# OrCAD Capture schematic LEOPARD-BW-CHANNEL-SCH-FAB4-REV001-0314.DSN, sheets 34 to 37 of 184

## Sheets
34 145_PVCCIN_CPU1_MOSFET_1: size C; title: PVCCIN_CPU1_MOSFET_1
35 144_PVCCIN_CPU1_Controller: size A3; title: PVCCIN_CPU1_CONTROLLER
36 143_PVCCIN_CPU0_Decoupling: size A3; title: PVCCIN_CPU0_DECOUPLING
37 142_PVCCIN_CPU0_MOSFET_2: size C; title: PVCCIN_CPU0_MOSFET_2

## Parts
sheet 142_PVCCIN_CPU0_MOSFET_2
PC1376  SCD47U25V3KX-3-GP  [C603H36]
PC1377  SC10U16V5KX-1-GP  [C805H54]
PC1378  SC10U16V5KX-1-GP  [C805H54]
PC1379  SC10U16V5KX-1-GP  [C805H54]
PC1380  SC1U10V2KX-4-GP  [C402H22]
PC1381  SCD22U16V2KX-GP  [C402H22]
PC1382  SC1U10V2KX-4-GP  [C402H22]
PC1383  SCD47U25V3KX-3-GP  [C603H36]
PC1384  SC10U16V5KX-1-GP  [C805H54]
PC1385  SC10U16V5KX-1-GP  [C805H54]
PC1386  SC10U16V5KX-1-GP  [C805H54]
PC1387  SCD22U16V2KX-GP  [C402H22]
PC1388  SC1U10V2KX-4-GP  [C402H22]
PC1406  SCD1U16V2KX-3GP  [C402H22]
PC1407  SC1U25V3KX-GP  [C603H36]
PC1408  SC1U25V3KX-GP  [C603H36]
PC1409  SCD1U16V2KX-3GP  [C402H22]
PC1410  SC1U10V2KX-4-GP  [C402H22]
PC1436  SCD1U16V2KX-3GP  [C402H22]
PC1437  SCD1U16V2KX-3GP  [C402H22]
PG35  COPPER-CLOSE-GP-U  [CON2C-U]
PG36  COPPER-CLOSE-GP-U  [CON2C-U]
PG39  COPPER-CLOSE-GP-U  [CON2C-U]
PG40  COPPER-CLOSE-GP-U  [CON2C-U]
PL78  IND-150NH-15-GP  [L102078-254224H296]
PL79  IND-150NH-15-GP  [L102078-254224H296]
PR27  0R2J-2-GP  [R402H16]
PR28  0R2J-2-GP  [R402H16]
PR45  0R2J-2-GP  [R402H16]
PR46  0R2J-2-GP  [R402H16]
PR2183  1R2F-GP  [R402H16]
PR2187  1R2F-GP  [R402H16]
PR2219  0R3J-6-GP  [R603H22]
PR2221  0R3J-6-GP  [R603H22]
PR2230  10KR2F-2-GP  [R402H16]
PR2231  10KR2F-2-GP  [R402H16]
PR6633  562R2F-GP  [R402H16]
PR6634  562R2F-GP  [R402H16]
PR6635  562R2F-GP  [R402H16]
PR6636  562R2F-GP  [R402H16]
PTP13  TPAD24  [TPAD24]
PTP14  TPAD24  [TPAD24]
PTP15  TPAD24  [TPAD24]
PTP16  TPAD24  [TPAD24]
PU181  TDA21232-GP  [QFN31G5-G4P-7H38]
PU182  TDA21232-GP  [QFN31G5-G4P-7H38]
sheet 143_PVCCIN_CPU0_Decoupling
PC38  SC1U10V2KX-4-GP  [C402H22]
PC39  SC1U10V2KX-4-GP  [C402H22]
PC1149  SC22U6D3V5MX-5-GP  [C805H56]
PC1150  SC22U6D3V5MX-5-GP  [C805H56]
PC1151  SC22U6D3V5MX-5-GP  [C805H56]
PC1152  SC22U6D3V5MX-5-GP  [C805H56]
PC1153  SC22U6D3V5MX-5-GP  [C805H56]
PC1154  SC22U6D3V5MX-5-GP  [C805H56]
PC1155  SC22U6D3V5MX-5-GP  [C805H56]
PC1156  SC22U6D3V5MX-5-GP  [C805H56]
PC1157  SC22U6D3V5MX-5-GP  [C805H56]
PC1158  SC22U6D3V5MX-5-GP  [C805H56]
PC1159  SC22U6D3V5MX-5-GP  [C805H56]
PC1160  SC22U6D3V5MX-5-GP  [C805H56]
PC1161  ST470U2D5VDM-13-GP  [CT7343H83]
PC1162  ST470U2D5VDM-13-GP  [CT7343H83]
PC1163  ST470U2D5VDM-13-GP  [CT7343H83]
PC1164  ST470U2D5VDM-13-GP  [CT7343H83]
PC1165  ST470U2D5VDM-13-GP  [CT7343H83]
PC1166  ST470U2D5VDM-13-GP  [CT7343H83]
PC1167  SC22U6D3V5MX-5-GP  [C805H56]
PC1168  SC22U6D3V5MX-5-GP  [C805H56]
PC1169  SC22U6D3V5MX-5-GP  [C805H56]
PC1170  SC22U6D3V5MX-5-GP  [C805H56]
PC1171  SC22U6D3V5MX-5-GP  [C805H56]
PC1172  SC22U6D3V5MX-5-GP  [C805H56]
PC1173  SC22U6D3V5MX-5-GP  [C805H56]
PC1174  SC22U6D3V5MX-5-GP  [C805H56]
PC1175  SC22U6D3V5MX-5-GP  [C805H56]
PC1176  SC22U6D3V5MX-5-GP  [C805H56]
PC1177  SC22U6D3V5MX-5-GP  [C805H56]
PC1178  SC22U6D3V5MX-5-GP  [C805H56]
PC1179  SC22U6D3V5MX-5-GP  [C805H56]
PC1180  SC22U6D3V5MX-5-GP  [C805H56]
PC1181  SC22U6D3V5MX-5-GP  [C805H56]
PC1182  SC22U6D3V5MX-5-GP  [C805H56]
PC1183  SC22U6D3V5MX-5-GP  [C805H56]
PC1184  SC47U4V5MX-2-GP  [C805H58]
PC1185  SC47U4V5MX-2-GP  [C805H58]
PC1186  SC47U4V5MX-2-GP  [C805H58]
PC1187  SC47U4V5MX-2-GP  [C805H58]
PC1188  SC47U4V5MX-2-GP  [C805H58]
PC1189  SC22U6D3V5MX-5-GP  [C805H56]
PC1190  SC22U6D3V5MX-5-GP  [C805H56]
PC1191  SC22U6D3V5MX-5-GP  [C805H56]
PC1192  SC22U6D3V5MX-5-GP  [C805H56]
PC1193  SC22U6D3V5MX-5-GP  [C805H56]
PC1194  SC22U6D3V5MX-5-GP  [C805H56]
PC1195  SC22U6D3V5MX-5-GP  [C805H56]
PC1196  SC22U6D3V5MX-5-GP  [C805H56]
PC1197  SC22U6D3V5MX-5-GP  [C805H56]
PC1198  SC22U6D3V5MX-5-GP  [C805H56]
PC1199  SC22U6D3V5MX-5-GP  [C805H56]
PC1200  SC22U6D3V5MX-5-GP  [C805H56]
PC1201  SC47U4V5MX-2-GP  [C805H58]
PC1202  SC47U4V5MX-2-GP  [C805H58]
PC1203  SC47U4V5MX-2-GP  [C805H58]
PC1204  SC47U4V5MX-2-GP  [C805H58]
PC1205  SC47U4V5MX-2-GP  [C805H58]
PC1206  SC47U4V5MX-2-GP  [C805H58]
PC1207  SC47U4V5MX-2-GP  [C805H58]
PC1208  SC47U4V5MX-2-GP  [C805H58]
PC1209  SC47U4V5MX-2-GP  [C805H58]
PC1210  SC47U4V5MX-2-GP  [C805H58]
PC1211  SC47U4V5MX-2-GP  [C805H58]
PC1212  SC47U4V5MX-2-GP  [C805H58]
PC1213  SC47U4V5MX-2-GP  [C805H58]
PC1214  SC47U4V5MX-2-GP  [C805H58]
PC1215  SC47U4V5MX-2-GP  [C805H58]
PC1216  SC47U4V5MX-2-GP  [C805H58]
PC1217  SC47U4V5MX-2-GP  [C805H58]
PC1218  SCD1U25V5KX-1GP  [C805H54]
PC1219  SC1U25V6KX-2GP  [C1206H45]
PC1220  SCD1U25V5KX-1GP  [C805H54]
PL60  IND-105NH-GP  [L7065-245152H195]
PR1949  100R2F-L1-GP-U  [R402H14]
PR1950  100R2F-L1-GP-U  [R402H14]
PTC15  E270U16VM-28-GP  [ECAP-100D6D3H363]
PTC16  E270U16VM-28-GP  [ECAP-100D6D3H363]
R6618  100R3F-1-GP  [R603H22]
sheet 144_PVCCIN_CPU1_Controller
PC1223  SC1U10V2KX-4-GP  [C402H22]
PC1224  SCD1U16V2KX-3GP  [C402H22]
PC1225  SC1U10V2KX-4-GP  [C402H22]
PC1226  SCD1U16V2KX-3GP  [C402H22]
PC1230  SC1KP50V2KX-1GP  [C402H22]
PC1231  SC10U4V3MX-3-GP  [C603H40]
PC1232  SC220P50V2KX-3GP  [C402H22]
PC1233  SCD1U16V2KX-3GP  [C402H22]
PC1460  SC220P50V2JN-3GP  [C402H22]
PC1586  SC220P50V2JN-3GP  [C402H22]
PC7326  SCD47U6D3V2KX-1-GP  [C402H22]
PC7327  SCD47U6D3V2KX-1-GP  [C402H22]
PC7328  SCD47U6D3V2KX-1-GP  [C402H22]
PC7329  SCD47U6D3V2KX-1-GP  [C402H22]
PC7330  SCD47U6D3V2KX-1-GP  [C402H22]
PQ7  NST3906F3T5G-GP-U  [SOT-1123CBE1006-1H16]
PR1937  0R2J-2-GP  [R402H16]
PR1951  0R2J-2-GP  [R402H16]
PR1952  10KR2F-2-GP  [R402H16]
PR1954  1KR2F-3-GP  [R402H16]
PR1955  1KR2F-3-GP  [R402H16]
PR1956  0R2J-2-GP  [R402H16]
PR1957  0R2J-2-GP  [R402H16]
PR1958  0R2J-2-GP  [R402H16]
PR1962  16KR2F-GP  [R402H16]
PR1963  16KR2F-GP  [R402H16]
PR1964  16KR2F-GP  [R402H16]
PR1965  19K1R2F-GP  [R402H16]
PR1966  1KR2F-3-GP  [R402H16]
PR1967  10R3F-GP  [R603H22]
PR1969  0R0402-PAD-1-GP  [0R0402-PAD]
PR1971  49D9R2F-GP  [R402H16]
PR1972  100R2F-L1-GP-U  [R402H14]
PR1973  82R2J-1-GP  [R402H16]
PR1974  0R2J-2-GP  [R402H16]
PR1975  0R2J-2-GP  [R402H16]
PR1976  150R2F-1-GP  [R402H16]
PTP2  TPAD24  [TPAD24]
PU7  PX3746HDN-GP  [QFN48J6-G3437H36]
sheet 145_PVCCIN_CPU1_MOSFET_1
PC1411  SCD47U25V3KX-3-GP  [C603H36]
PC1412  SC10U16V5KX-1-GP  [C805H54]
PC1413  SC10U16V5KX-1-GP  [C805H54]
PC1414  SC10U16V5KX-1-GP  [C805H54]
PC1415  SCD1U16V2KX-3GP  [C402H22]
PC1416  SC1U25V3KX-GP  [C603H36]
PC1417  SCD22U16V2KX-GP  [C402H22]
PC1418  SC1U10V2KX-4-GP  [C402H22]
PC1419  SC1U10V2KX-4-GP  [C402H22]
PC1420  SCD47U25V3KX-3-GP  [C603H36]
PC1421  SC10U16V5KX-1-GP  [C805H54]
PC1422  SC10U16V5KX-1-GP  [C805H54]
PC1438  SCD1U16V2KX-3GP  [C402H22]
PC1439  SC10U16V5KX-1-GP  [C805H54]
PC1440  SCD1U16V2KX-3GP  [C402H22]
PC1441  SC1U25V3KX-GP  [C603H36]
PC1442  SCD1U16V2KX-3GP  [C402H22]
PC1443  SC1U10V2KX-4-GP  [C402H22]
PC1444  SCD22U16V2KX-GP  [C402H22]
PC1445  SC1U10V2KX-4-GP  [C402H22]
PC1446  SCD47U25V3KX-3-GP  [C603H36]
PC1447  SC10U16V5KX-1-GP  [C805H54]
PC1448  SC10U16V5KX-1-GP  [C805H54]
PC1449  SC10U16V5KX-1-GP  [C805H54]
PC1450  SCD1U16V2KX-3GP  [C402H22]
PC1451  SC1U25V3KX-GP  [C603H36]
PC1452  SCD1U16V2KX-3GP  [C402H22]
PC1453  SCD22U16V2KX-GP  [C402H22]
PC1454  SC1U10V2KX-4-GP  [C402H22]
PC1455  SC1U10V2KX-4-GP  [C402H22]
PG41  COPPER-CLOSE-GP-U  [CON2C-U]
PG42  COPPER-CLOSE-GP-U  [CON2C-U]
PG47  COPPER-CLOSE-GP-U  [CON2C-U]
PG48  COPPER-CLOSE-GP-U  [CON2C-U]
PG55  COPPER-CLOSE-GP-U  [CON2C-U]
PG56  COPPER-CLOSE-GP-U  [CON2C-U]
PL80  IND-150NH-15-GP  [L102078-254224H296]
PL81  IND-150NH-15-GP  [L102078-254224H296]
PL82  IND-150NH-15-GP  [L102078-254224H296]
PR29  0R2J-2-GP  [R402H16]
PR30  0R2J-2-GP  [R402H16]
PR31  0R2J-2-GP  [R402H16]
PR47  0R2J-2-GP  [R402H16]
PR48  0R2J-2-GP  [R402H16]
PR49  0R2J-2-GP  [R402H16]
PR2190  1R2F-GP  [R402H16]
PR2193  1R2F-GP  [R402H16]
PR2196  1R2F-GP  [R402H16]
PR2223  0R3J-6-GP  [R603H22]
PR2225  0R3J-6-GP  [R603H22]
PR2232  10KR2F-2-GP  [R402H16]
PR2233  10KR2F-2-GP  [R402H16]
PR2234  10KR2F-2-GP  [R402H16]
PR2237  0R3J-6-GP  [R603H22]
PR6637  562R2F-GP  [R402H16]
PR6638  562R2F-GP  [R402H16]
PR6639  562R2F-GP  [R402H16]
PR6640  562R2F-GP  [R402H16]
PR6641  562R2F-GP  [R402H16]
PR6642  562R2F-GP  [R402H16]
PTP17  TPAD24  [TPAD24]
PTP18  TPAD24  [TPAD24]
PTP19  TPAD24  [TPAD24]
PTP20  TPAD24  [TPAD24]
PTP21  TPAD24  [TPAD24]
PTP22  TPAD24  [TPAD24]
PU183  TDA21232-GP  [QFN31G5-G4P-7H38]
PU184  TDA21232-GP  [QFN31G5-G4P-7H38]
PU185  TDA21232-GP  [QFN31G5-G4P-7H38]

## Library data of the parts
PC1376 PC1383 PC1411 PC1420 PC1446 = SCD47U25V3KX-3-GP: CHIP CAP C 0.47U 25V K0603 X7R; GREENDFACTOR: R2_SA;HF_SA;G_SA;; Part Number: 78.47422.2BL; Part Type: SMD-BCG5; SPEC: http://wpqssvr.wistron.com.tw:7001/wpqs/servlet/COM.qpart.Attachment?PartNumber=78.47422.2BL
PC1377-PC1379 PC1384-PC1386 PC1412-PC1414 PC1421 PC1422 PC1439 PC1447-PC1449 = SC10U16V5KX-1-GP: CHIP CAP C 10U 16V K0805 X6S; GREENDFACTOR: R2_SA;; Package Type: SMD-BCG5; Part Number: 78.10621.81L; SPEC: http://wpqssvr.wistron.com.tw:7001/wpqs/servlet/COM.qpart.Attachment?PartNumber=78.10621.81L
PC1223 PC1225 PC1380 PC1382 PC1388 PC1410 PC1418 PC1419 PC1443 PC1445 PC1454 PC1455 = SC1U10V2KX-4-GP: CHIP CAP C 1U 10V K 0402 X6S; GREENDFACTOR: R2_SA;HF_SA;; Package Type: SMD-BCG6; Part Number: 78.10523.8FL; SPEC: http://wpqssvr.wistron.com.tw:7001/wpqs/servlet/COM.qpart.Attachment?PartNumber=78.10523.8FL
PC1381 PC1387 PC1417 PC1444 PC1453 = SCD22U16V2KX-GP: CHIP CAP C 0.22U 16V K0402 X7R; GREENDFACTOR: R2_SA;HF_SA;G_SA;; Package Type: SMD-BCG4; Part Number: 78.22421.2FL; SPEC: http://wpqssvr.wistron.com.tw:7001/wpqs/servlet/COM.qpart.Attachment?PartNumber=78.22421.2FL; Size: 0402; Type: X7R
PC1406 PC1409 PC1415 PC1436-PC1438 PC1440 PC1442 PC1450 PC1452 = SCD1U16V2KX-3GP: CHIP CAP C 0.1U 16V K0402 X7R; GREENDFACTOR: R2_SA;HF_SA;G_SA;; MAIN_SOURCE: M; Package Type: SMD-BCG; Part Number: 78.10421.2FL; SPEC: http://wpqssvr.wistron.com.tw:7001/wpqs/servlet/COM.qpart.Attachment?PartNumber=78.10421.2FL; Size: 0402; Type: X7R
PC1407 PC1408 PC1416 PC1441 PC1451 = SC1U25V3KX-GP: CHIP CAP C 1U 25V K0603 X7R; GREENDFACTOR: R2_SA;HF_SA;G_SA;; Package Type: SMD-BCG; Part Number: 78.10522.2BL; SPEC: http://wpqssvr.wistron.com.tw:7001/wpqs/servlet/COM.qpart.Attachment?PartNumber=78.10522.2BL
PG35 PG36 PG39-PG42 PG47 PG48 PG55 PG56 = COPPER-CLOSE-GP-U: COPPER CLOSE; GREENDFACTOR: Regular;; Package Type: DISCRET-G9; Part Number: ZZ.CON2C.XXX; SPEC: http://wpqssvr.wistron.com.tw:7001/wpqs/servlet/COM.qpart.Attachment?PartNumber=ZZ.CON2C.XXX
PL78-PL82 = IND-150NH-15-GP: CHIP IND 150NH K FP1007R3-R15-R; GREENDFACTOR: R2_SA;; Part Number: 68.1512N.10E; Part Type: DISCRET-G9; SPEC: http://wpqssvr.wistron.com.tw:7001/wpqs/servlet/COM.qpart.Attachment?PartNumber=68.1512N.10E
PR27-PR31 = 0R2J-2-GP: CHIP RES 0 J 1/16W 0402; GREENDFACTOR: R2_SA;HF_SA;G_SA;; POP?: NOPOP; Package Type: SMD-RG; Part Number: 63.R0034.1DL; SPEC: http://wpqssvr.wistron.com.tw:7001/wpqs/servlet/COM.qpart.Attachment?PartNumber=63.R0034.1DL
PR45-PR49 PR1951 PR1956-PR1958 PR1974 PR1975 = 0R2J-2-GP: CHIP RES 0 J 1/16W 0402; GREENDFACTOR: R2_SA;HF_SA;G_SA;; Package Type: SMD-RG; Part Number: 63.R0034.1DL; SPEC: http://wpqssvr.wistron.com.tw:7001/wpqs/servlet/COM.qpart.Attachment?PartNumber=63.R0034.1DL
PR2183 PR2187 PR2190 PR2193 PR2196 = 1R2F-GP: CHIP RES 1 F 1/16W 0402; GREENDFACTOR: R2_SA;HF_SA;G_SA;; Package Type: SMD-RG; Part Number: 64.1R005.6DL; SPEC: http://wpqssvr.wistron.com.tw:7001/wpqs/servlet/COM.qpart.Attachment?PartNumber=64.1R005.6DL
PR2219 PR2221 PR2223 PR2225 PR2237 = 0R3J-6-GP: CHIP RES 0 J 1/10W 0603; GREENDFACTOR: R2_SA;HF_SA;G_SA;; Part Number: 63.R0033.15L; Part Type: SMD-RG1; SPEC: http://wpqssvr.wistron.com.tw:7001/wpqs/servlet/COM.qpart.Attachment?PartNumber=63.R0033.15L
PR2230-PR2234 = 10KR2F-2-GP: CHIP RES 10K F 1/16W 0402; GREENDFACTOR: R2_SA;HF_SA;G_SA;; POP?: NOPOP; Package Type: SMD-RG; Part Number: 64.10025.6DL; SPEC: http://wpqssvr.wistron.com.tw:7001/wpqs/servlet/COM.qpart.Attachment?PartNumber=64.10025.6DL
PR6633-PR6642 = 562R2F-GP: CHIP RES 562 F 1/16W 0402; GREENDFACTOR: R2_SA;HF_SA;G_SA;; Package Type: SMD-RG; Part Number: 64.56205.6DL; SPEC: http://wpqssvr.wistron.com.tw:7001/wpqs/servlet/COM.qpart.Attachment?PartNumber=64.56205.6DL
PTP2 PTP13-PTP22 = TPAD24: 24 MILS TEST PAD; GREENDFACTOR: Regular;; Package Type: DISCRET2; Part Number: ZZ.PAD24.001; SPEC: http://wpqssvr.wistron.com.tw:7001/wpqs/servlet/COM.qpart.Attachment?PartNumber=ZZ.PAD24.001
PU181-PU185 = TDA21232-GP: IC PWM TDA21232 IQFN 32P; GREENDFACTOR: R2_C;; Part Number: 074.21232.0073; Part Type: DISCRET-GB1; SPEC: http://wpqssvr.wistron.com.tw:7001/wpqs/servlet/COM.qpart.Attachment?PartNumber=074.21232.0073
PC38 PC39 = SC1U10V2KX-4-GP: CHIP CAP C 1U 10V K 0402 X6S; GREENDFACTOR: R2_SA;HF_SA;; Part Number: 78.10523.8FL; Part Type: SMD-BCG6; SPEC: http://wpqssvr.wistron.com.tw:7001/wpqs/servlet/COM.qpart.Attachment?PartNumber=78.10523.8FL
PC1149-PC1160 PC1167-PC1178 PC1189-PC1200 = SC22U6D3V5MX-5-GP: CHIP CAP C 22U 6.3V M0805 X6S; GREENDFACTOR: R2_SA;HF_SA;G_SA;; Package Type: SMD-BCG2; Part Number: 78.22610.81L; SPEC: http://wpqssvr.wistron.com.tw:7001/wpqs/servlet/COM.qpart.Attachment?PartNumber=78.22610.81L; Size: 0805; Type: X6S
PC1161-PC1166 = ST470U2D5VDM-13-GP: CHIP CAP EL 470U 2.5V M7343 ESR4.5 SX; GREENDFACTOR: R2_C;HF_C;; Module: VR_PVCORE_CPU; Package Type: SMD-TCG5; Part Number: 79.4771V.6AL; Part_Spec: 470uF/2.5V/4.5mohm; Quotation: 8_1; SPEC: http://wpqssvr.wistron.com.tw:7001/wpqs/servlet/COM.qpart.Attachment?PartNumber=79.4771V.6AL; VENDOR_PN: EEFSX0E471E4
PC1179-PC1183 = SC22U6D3V5MX-5-GP: CHIP CAP C 22U 6.3V M0805 X6S; GREENDFACTOR: R2_SA;HF_SA;G_SA;; Package Type: SMD-BCG2; Part Number: 78.22610.81L; SPEC: http://wpqssvr.wistron.com.tw:7001/wpqs/servlet/COM.qpart.Attachment?PartNumber=78.22610.81L
PC1184-PC1188 PC1201-PC1217 = SC47U4V5MX-2-GP: CHIP CAP C 47U 4V M0805 X6S; GREENDFACTOR: R2_SA;HF_SA;G_SA;; Package Type: SMD-BCG3; Part Number: 78.4761T.81L; SPEC: http://wpqssvr.wistron.com.tw:7001/wpqs/servlet/COM.qpart.Attachment?PartNumber=78.4761T.81L
PC1218 PC1220 = SCD1U25V5KX-1GP: CHIP CAP0.1U25V K0805 X7R(ROHS; GREENDFACTOR: R2_SA;HF_SA;G_SA;; Package Type: SMD-BCG; Part Number: 78.10422.21L; SPEC: http://wpqssvr.wistron.com.tw:7001/wpqs/servlet/COM.qpart.Attachment?PartNumber=78.10422.21L
PC1219 = SC1U25V6KX-2GP: CHIP CAP C 1U 25V K1206 X7R; GREENDFACTOR: R2_SA;HF_SA;G_SA;; Package Type: SMD-BCG1; Part Number: 78.10522.22L; SPEC: http://wpqssvr.wistron.com.tw:7001/wpqs/servlet/COM.qpart.Attachment?PartNumber=78.10522.22L
PL60 = IND-105NH-GP: CHIP IND 105NH K FP0705R1-R10-R; GREENDFACTOR: R2_C;; Package Type: DISCRET-G7; Part Number: 68.1052N.101; Part_Spec: 0.105uH/36A/0.25mohm; SPEC: http://wpqssvr.wistron.com.tw:7001/wpqs/servlet/COM.qpart.Attachment?PartNumber=68.1052N.101; Vendor_PN: FP0705R1-R10-R
PR1949 PR1950 PR1972 = 100R2F-L1-GP-U: CHIP RES 100 F 1/16W 0402; GREENDFACTOR: R2_SA;HF_SA;G_SA;; Package Type: SMD-RG; Part Number: 64.10005.6DL; SPEC: http://wpqssvr.wistron.com.tw:7001/wpqs/servlet/COM.qpart.Attachment?PartNumber=64.10005.6DL
PTC15 PTC16 = E270U16VM-28-GP: CAP EL 270U 16V RT2.5 6.3*8 SOLID CAP; GREENDFACTOR: R2_SA;HF_SA;; Part Number: 09.2771D.E4L; Part Spec: 270uF/16V/10mohm/5A; Part Type: DIP-TCG4; SPEC: http://wpqssvr.wistron.com.tw:7001/wpqs/servlet/COM.qpart.Attachment?PartNumber=09.2771D.E4L
R6618 = 100R3F-1-GP: CHIP RES 100 F 1/10W 0603(ROHS; GREENDFACTOR: R2_SA;HF_SA;G_SA;; Package Type: SMD-RG6; Part Number: 64.10005.55L; SPEC: http://wpqssvr.wistron.com.tw:7001/wpqs/servlet/COM.qpart.Attachment?PartNumber=64.10005.55L
PC1224 PC1226 = SCD1U16V2KX-3GP: CHIP CAP C 0.1U 16V K0402 X7R; GREENDFACTOR: R2_SA;HF_SA;G_SA;; MAIN_SOURCE: M; Package Type: SMD-BCG; Part Number: 78.10421.2FL; SPEC: http://wpqssvr.wistron.com.tw:7001/wpqs/servlet/COM.qpart.Attachment?PartNumber=78.10421.2FL
PC1230 = SC1KP50V2KX-1GP: CHIP CAP 1000P50V K0402 X7R(RO; GREENDFACTOR: R2_SA;HF_SA;G_SA;; MAIN_SOURCE: M; Package Type: SMD-BCG; Part Number: 78.10224.2FL; SPEC: http://wpqssvr.wistron.com.tw:7001/wpqs/servlet/COM.qpart.Attachment?PartNumber=78.10224.2FL
PC1231 = SC10U4V3MX-3-GP: CHIP CAP C 10U 4V M0603 X6S; GREENDFACTOR: R2_C;; POP?: 078.1061T.08B1; Package Type: SMD-BCG6; Part Number: 78.1061T.8BL; SPEC: http://wpqssvr.wistron.com.tw:7001/wpqs/servlet/COM.qpart.Attachment?PartNumber=78.1061T.8BL
PC1232 = SC220P50V2KX-3GP: CHIP CAP 220P50V K0402 X7R(ROH; GREENDFACTOR: R2_SA;HF_SA;G_SA;; MAIN_SOURCE: M; Package Type: SMD-BCG; Part Number: 78.22124.2FL; SPEC: http://wpqssvr.wistron.com.tw:7001/wpqs/servlet/COM.qpart.Attachment?PartNumber=78.22124.2FL
PC1233 = SCD1U16V2KX-3GP: CHIP CAP C 0.1U 16V K0402 X7R; CATEGORIES: CAP_1.xV; GREENDFACTOR: R2_SA;HF_SA;G_SA;; MAIN_SOURCE: M; Part Number: 78.10421.2FL; Part Type: SMD-BCG; SPEC: http://wpqssvr.wistron.com.tw:7001/wpqs/servlet/COM.qpart.Attachment?PartNumber=78.10421.2FL
PC1460 PC1586 = SC220P50V2JN-3GP: CHIP CAP C 220P 50V J0402 NPO; GREENDFACTOR: R2_SA;HF_SA;G_SA;; Package Type: SMD-BCG; Part Number: 78.22134.1FL; SPEC: http://wpqssvr.wistron.com.tw:7001/wpqs/servlet/COM.qpart.Attachment?PartNumber=78.22134.1FL
PC7326-PC7330 = SCD47U6D3V2KX-1-GP: CHIP CAP C 0.47U 6.3V K 0402 X6S; GREENDFACTOR: R2_SA;HF_SA;; Package Type: SMD-BCG3; Part Number: 78.47420.8FL; SPEC: http://wpqssvr.wistron.com.tw:7001/wpqs/servlet/COM.qpart.Attachment?PartNumber=78.47420.8FL
PQ7 = NST3906F3T5G-GP-U: XTOR NST3906F3T5G PNP SOT-1123; GREENDFACTOR: R2_SA;HF_SA;; Package Type: DISCRET-G5; Part Number: 84.03906.01K; SPEC: http://wpqssvr.wistron.com.tw:7001/wpqs/servlet/COM.qpart.Attachment?PartNumber=84.03906.01K
PR1937 = 0R2J-2-GP: CHIP RES 0 J 1/16W 0402; GREENDFACTOR: R2_SA;HF_SA;G_SA;; Part Number: 63.R0034.1DL; Part Type: SMD-RG; SPEC: http://wpqssvr.wistron.com.tw:7001/wpqs/servlet/COM.qpart.Attachment?PartNumber=63.R0034.1DL
PR1952 = 10KR2F-2-GP: CHIP RES 10K F 1/16W 0402; GREENDFACTOR: R2_SA;HF_SA;G_SA;; Package Type: SMD-RG; Part Number: 64.10025.6DL; SPEC: http://wpqssvr.wistron.com.tw:7001/wpqs/servlet/COM.qpart.Attachment?PartNumber=64.10025.6DL
PR1954 PR1955 PR1966 = 1KR2F-3-GP: CHIP RES 1K F 1/16W 0402; GREENDFACTOR: R2_SA;HF_SA;G_SA;; Package Type: SMD-RG; Part Number: 64.10015.6DL; SPEC: http://wpqssvr.wistron.com.tw:7001/wpqs/servlet/COM.qpart.Attachment?PartNumber=64.10015.6DL
PR1962 = 16KR2F-GP: CHIP RES 16K F 1/16W 0402; GREENDFACTOR: R2_SA;HF_SA;G_SA;; Module: VR_PVCORE_CPU; POP?: NOPOP; Package Type: SMD-RG; Part Number: 64.16025.6DL; Quotation: 8_1; SPEC: http://wpqssvr.wistron.com.tw:7001/wpqs/servlet/COM.qpart.Attachment?PartNumber=64.16025.6DL
PR1963 PR1964 = 16KR2F-GP: CHIP RES 16K F 1/16W 0402; GREENDFACTOR: R2_SA;HF_SA;G_SA;; Module: VR_PVCORE_CPU; Package Type: SMD-RG; Part Number: 64.16025.6DL; Quotation: 8_1; SPEC: http://wpqssvr.wistron.com.tw:7001/wpqs/servlet/COM.qpart.Attachment?PartNumber=64.16025.6DL
PR1965 = 19K1R2F-GP: CHIP RES 19.1K F 1/16W 0402; GREENDFACTOR: R2_SA;HF_SA;G_SA;; Part Number: 64.19125.6DL; Part Type: RCL_GP; SPEC: http://wpqssvr.wistron.com.tw:7001/wpqs/servlet/COM.qpart.Attachment?PartNumber=64.19125.6DL
PR1967 = 10R3F-GP: CHIP RES 10 F 1/10W 0603; GREENDFACTOR: R2_SA;HF_SA;G_SA;; Level: SMD; Package Type: RCL_GP; Part Number: 64.10R05.55L; Part Type: RCL_GP; SPEC: http://wpqssvr.wistron.com.tw:7001/wpqs/servlet/COM.qpart.Attachment?PartNumber=64.10R05.55L; Status: POP
PR1969 = 0R0402-PAD-1-GP: DUMMY PAD WITH WIRE RES 0 0402; GREENDFACTOR: R_C;; Module: VR_CPU_PVCC; Package Type: SMD-RG2; Part Number: ZZ.R0402.001; Part Type: SMD-RG2; Quotation: 8_1; SPEC: http://wpqssvr.wistron.com.tw:7001/wpqs/servlet/COM.qpart.Attachment?PartNumber=ZZ.R0402.001
PR1971 = 49D9R2F-GP: CHIP RES 49.9 F 1/16W 0402; GREENDFACTOR: R2_SA;HF_SA;G_SA;; Package Type: RCL_GP; Part Number: 64.49R95.6DL; SPEC: http://wpqssvr.wistron.com.tw:7001/wpqs/servlet/COM.qpart.Attachment?PartNumber=64.49R95.6DL
PR1973 = 82R2J-1-GP: CHIP RES 82 J 1/16W 0402; GREENDFACTOR: R2_SA;HF_SA;G_SA;; POP?: NOPOP; Package Type: RCL_GP; Part Number: 63.82034.1DL; SPEC: http://wpqssvr.wistron.com.tw:7001/wpqs/servlet/COM.qpart.Attachment?PartNumber=63.82034.1DL
PR1976 = 150R2F-1-GP: CHIP RES 150 F 1/16W 0402; GREENDFACTOR: R2_SA;HF_SA;G_SA;; Package Type: SMD-RG; Part Number: 64.15005.6DL; SPEC: http://wpqssvr.wistron.com.tw:7001/wpqs/servlet/COM.qpart.Attachment?PartNumber=64.15005.6DL
PU7 = PX3746HDN-GP: IC PWM CTRL PX3746HDN QFN 48P; GREENDFACTOR: R2_SA;; Package Type: ASIC-G5; Part Number: 074.03746.0073; SPEC: http://wpqssvr.wistron.com.tw:7001/wpqs/servlet/COM.qpart.Attachment?PartNumber=074.03746.0073

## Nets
GND: PC38.2 PC39.2 PC1149.2 PC1150.2 PC1151.2 PC1152.2 PC1153.2 PC1154.2 PC1155.2 PC1156.2 PC1157.2 PC1158.2 PC1159.2 PC1160.2 PC1161.2 PC1162.2 PC1163.2 PC1164.2 PC1165.2 PC1166.2 PC1167.2 PC1168.2 PC1169.2 PC1170.2 PC1171.2 PC1172.2 PC1173.2 PC1174.2 PC1175.2 PC1176.2 PC1177.2 PC1178.2 PC1179.2 PC1180.2 PC1181.2 PC1182.2 PC1183.2 PC1184.2 PC1185.2 PC1186.2 PC1187.2 PC1188.2 PC1189.2 PC1190.2 PC1191.2 PC1192.2 PC1193.2 PC1194.2 PC1195.2 PC1196.2 PC1197.2 PC1198.2 PC1199.2 PC1200.2 PC1201.2 PC1202.2 PC1203.2 PC1204.2 PC1205.2 PC1206.2 PC1207.2 PC1208.2 PC1209.2 PC1210.2 PC1211.2 PC1212.2 PC1213.2 PC1214.2 PC1215.2 PC1216.2 PC1217.2 PC1218.2 PC1219.2 PC1220.2 PC1223.2 PC1224.2 PC1225.2 PC1226.2 PC1230.1 PC1231.2 PC1233.2 PC1377.2 PC1378.2 PC1379.2 PC1380.1 PC1381.1 PC1382.1 PC1384.2 PC1385.2 PC1386.2 PC1387.1 PC1388.1 PC1406.2 PC1407.2 PC1408.2 PC1409.2 PC1410.1 PC1412.2 PC1413.2 PC1414.2 PC1415.2 PC1416.2 PC1417.1 PC1418.1 PC1419.1 PC1421.2 PC1422.2 PC1436.2 PC1437.2 PC1438.2 PC1439.2 PC1440.2 PC1441.2 PC1442.2 PC1443.1 PC1444.1 PC1445.1 PC1447.2 PC1448.2 PC1449.2 PC1450.2 PC1451.2 PC1452.2 PC1453.1 PC1454.1 PC1455.1 PC1460.1 PC1586.1 PQ7.B PQ7.C PR27.2 PR28.2 PR29.2 PR30.2 PR31.2 PR1950.1 PR1962.2 PR1963.2 PR1964.2 PR1966.1 PTC15.2 PTC16.2 PU7.1(GND) PU7.20(ISEN6N) PU7.38(GND) PU7.39(GND) PU7.41(GND) PU7.42(GND) PU7.44(GND) PU7.49(GND) PU181.4(AGND) PU181.12(PGND) PU181.13(PGND) PU181.14(PGND) PU181.15(PGND) PU181.28(PGND) PU181.32(PGND) PU181.34(PGND) PU182.4(AGND) PU182.12(PGND) PU182.13(PGND) PU182.14(PGND) PU182.15(PGND) PU182.28(PGND) PU182.32(PGND) PU182.34(PGND) PU183.4(AGND) PU183.12(PGND) PU183.13(PGND) PU183.14(PGND) PU183.15(PGND) PU183.28(PGND) PU183.32(PGND) PU183.34(PGND) PU184.4(AGND) PU184.12(PGND) PU184.13(PGND) PU184.14(PGND) PU184.15(PGND) PU184.28(PGND) PU184.32(PGND) PU184.34(PGND) PU185.4(AGND) PU185.12(PGND) PU185.13(PGND) PU185.14(PGND) PU185.15(PGND) PU185.28(PGND) PU185.32(PGND) PU185.34(PGND) R6618.2 ; also on sheet 1 2 3 4 5 6 7 8 9 10 11 12 13 14 15 16 17 18 19 20 21 22 23 24 25 26 27 28 29 30 31 32 33 38 39 44 46 47 49 50 51 52 53 54 55 56 57 58 59 60 61 62 63 64 65 66 69 70 71 73 74 75 76 78 79 80 81 82 83 84 86 87 88 89 90 91 92 93 94 95 96 97 98 99 100 101 102 103 104 105 106 107 108 109 110 111 112 113 114 115 116 117 118 119 128 129 138 139 159 160 161 166 168 169 170 171 172 173 174 175 176 177 180 181 182 183 184
P3V3_STBY: PR45.2 PR46.2 PR47.2 PR48.2 PR49.2 PR1951.1 PR1952.2 PR1954.2 PR1955.2 ; also on sheet 2 3 5 6 8 9 10 11 12 15 16 17 20 21 22 25 26 27 30 31 33 38 39 45 47 49 50 51 52 54 55 59 60 61 62 63 64 65 66 69 70 71 72 73 74 76 79 83 84 87 88 89 90 91 92 93 94 95 96 97 98 99 159 161 166 168 173 174 176 177 179 180 182 183 184
P5V_STBY: PC1381.2 PC1382.2 PC1387.2 PC1410.2 PC1417.2 PC1419.2 PC1444.2 PC1445.2 PC1453.2 PC1455.2 PR2183.1 PR2187.1 PR2190.1 PR2193.1 PR2196.1 PU181.29(PVCC) PU182.29(PVCC) PU183.29(PVCC) PU184.29(PVCC) PU185.29(PVCC) ; also on sheet 4 5 6 8 14 15 19 20 24 25 29 30 33 38 59 61 65 69 76 95
P12V_STBY: PC1218.1 PC1219.1 PL60.1 ; also on sheet 2 3 4 7 9 10 11 12 13 17 18 22 23 27 28 32 59 60 75 95 104 105 106 107 108 109 110 111 112 113 114 115 116 117 118 119
PVCCIN_CPU0: PC38.1 PC39.1 PC1149.1 PC1150.1 PC1151.1 PC1152.1 PC1153.1 PC1154.1 PC1155.1 PC1156.1 PC1157.1 PC1158.1 PC1159.1 PC1160.1 PC1161.1 PC1162.1 PC1163.1 PC1164.1 PC1165.1 PC1166.1 PC1167.1 PC1168.1 PC1169.1 PC1170.1 PC1171.1 PC1172.1 PC1173.1 PC1174.1 PC1175.1 PC1176.1 PC1177.1 PC1178.1 PC1179.1 PC1180.1 PC1181.1 PC1182.1 PC1183.1 PC1184.1 PC1185.1 PC1186.1 PC1187.1 PC1188.1 PC1189.1 PC1190.1 PC1191.1 PC1192.1 PC1193.1 PC1194.1 PC1195.1 PC1196.1 PC1197.1 PC1198.1 PC1199.1 PC1200.1 PC1201.1 PC1202.1 PC1203.1 PC1204.1 PC1205.1 PC1206.1 PC1207.1 PC1208.1 PC1209.1 PC1210.1 PC1211.1 PC1212.1 PC1213.1 PC1214.1 PC1215.1 PC1216.1 PC1217.1 PG36.2 PG40.2 PL78.2(F) PL79.2(F) PR1949.1 R6618.1 ; also on sheet 38 130
PVCCIN_CPU0_BOOT4: PR2219.1 PU182.5(BOOT)
PVCCIN_CPU0_BOOT5: PR2221.1 PU181.5(BOOT)
PVCCIN_CPU0_EN4: PR45.1 PU182.31(EN)
PVCCIN_CPU0_EN5: PR46.1 PU181.31(EN)
PVCCIN_CPU0_GH4: PTP16.1 PU182.6(GH)
PVCCIN_CPU0_GH5: PTP14.1 PU181.6(GH)
PVCCIN_CPU0_GL4: PTP15.1 PU182.27(GL#27)
PVCCIN_CPU0_GL5: PTP13.1 PU181.27(GL#27)
PVCCIN_CPU0_ISEN4N: PR6636.2 ; also on sheet 39
PVCCIN_CPU0_ISEN4P: PG36.1 ; also on sheet 39
PVCCIN_CPU0_ISEN5N: PR6633.2 ; also on sheet 39
PVCCIN_CPU0_ISEN5P: PG40.1 ; also on sheet 39
PVCCIN_CPU0_PHASE4: PC1383.2 PU182.7(PHASE)
PVCCIN_CPU0_PHASE4_R: PC1383.1 PR2219.2
PVCCIN_CPU0_PHASE5: PC1376.2 PU181.7(PHASE)
PVCCIN_CPU0_PHASE5_R: PC1376.1 PR2221.2
PVCCIN_CPU0_PWM4: PU182.1(PWM) ; also on sheet 39
PVCCIN_CPU0_PWM5: PU181.1(PWM) ; also on sheet 39
PVCCIN_CPU0_SW#4: PG35.2 PL79.1(S) PU182.16(SW#16) PU182.17(SW#17) PU182.18(SW#18) PU182.19(SW#19) PU182.20(SW#20) PU182.21(SW#21) PU182.22(SW#22) PU182.23(SW#23) PU182.24(NC#24) PU182.25(NC#25) PU182.26(NC#26)
PVCCIN_CPU0_SW#4_N: PG35.1 PR6635.2
PVCCIN_CPU0_SW#4_R: PR6635.1 PR6636.1
PVCCIN_CPU0_SW#5: PG39.2 PL78.1(S) PU181.16(SW#16) PU181.17(SW#17) PU181.18(SW#18) PU181.19(SW#19) PU181.20(SW#20) PU181.21(SW#21) PU181.22(SW#22) PU181.23(SW#23) PU181.24(NC#24) PU181.25(NC#25) PU181.26(NC#26)
PVCCIN_CPU0_SW#5_N: PG39.1 PR6634.2
PVCCIN_CPU0_SW#5_R: PR6633.1 PR6634.1
PVCCIN_CPU0_TMON4: PR27.1 PU182.30(PHFLT#)
PVCCIN_CPU0_TMON5: PR28.1 PU181.30(PHFLT#)
PVCCIN_CPU0_VCC4: PC1388.2 PR2187.2 PR2231.2 PU182.3(VCC)
PVCCIN_CPU0_VCC5: PC1380.2 PR2183.2 PR2230.2 PU181.3(VCC)
PVCCIN_CPU0_VIN: PC1220.1 PC1377.1 PC1378.1 PC1379.1 PC1384.1 PC1385.1 PC1386.1 PC1406.1 PC1407.1 PC1408.1 PC1409.1 PC1436.1 PC1437.1 PL60.2 PTC15.1 PTC16.1 PU181.8(VIN) PU181.9(VIN) PU181.10(VIN) PU181.11(VIN) PU181.33(VIN) PU182.8(VIN) PU182.9(VIN) PU182.10(VIN) PU182.11(VIN) PU182.33(VIN) ; also on sheet 38 39
PVCCIN_CPU0_ZCD#4: PR2231.1 PU182.2(NC#2)
PVCCIN_CPU0_ZCD#5: PR2230.1 PU181.2(NC#2)
PVCCIN_CPU1: PG42.2 PG48.2 PG56.2 PL80.2(F) PL81.2(F) PL82.2(F) ; also on sheet 32 33 120
PVCCIN_CPU1_ALERT: PR1974.1 PU7.15(ALERT#)
PVCCIN_CPU1_BOOT1: PR2223.1 PU184.5(BOOT)
PVCCIN_CPU1_BOOT2: PR2225.1 PU183.5(BOOT)
PVCCIN_CPU1_BOOT3: PR2237.1 PU185.5(BOOT)
PVCCIN_CPU1_EN: PR1957.2 ; also on sheet 51
PVCCIN_CPU1_EN1: PR47.1 PU184.31(EN)
PVCCIN_CPU1_EN2: PR48.1 PU183.31(EN)
PVCCIN_CPU1_EN3: PR49.1 PU185.31(EN)
PVCCIN_CPU1_FAULT: PR1952.1 PR1956.1 PU7.46(FAULT1)
PVCCIN_CPU1_GH1: PTP20.1 PU184.6(GH)
PVCCIN_CPU1_GH2: PTP18.1 PU183.6(GH)
PVCCIN_CPU1_GH3: PTP22.1 PU185.6(GH)
PVCCIN_CPU1_GL1: PTP19.1 PU184.27(GL#27)
PVCCIN_CPU1_GL2: PTP17.1 PU183.27(GL#27)
PVCCIN_CPU1_GL3: PTP21.1 PU185.27(GL#27)
PVCCIN_CPU1_IMON: PTP2.1 PU7.22(IMON/FAULT2)
PVCCIN_CPU1_ISEN1N: PC7326.2 PR6640.2 PU7.34(ISEN1N)
PVCCIN_CPU1_ISEN1P: PC7326.1 PG42.1 PU7.35(ISEN1P)
PVCCIN_CPU1_ISEN2N: PC7327.2 PR6637.2 PU7.31(ISEN2N)
PVCCIN_CPU1_ISEN2P: PC7327.1 PG48.1 PU7.32(ISEN2P)
PVCCIN_CPU1_ISEN3N: PC7328.2 PR6641.2 PU7.28(ISEN3N)
PVCCIN_CPU1_ISEN3P: PC7328.1 PG56.1 PU7.29(ISEN3P)
PVCCIN_CPU1_ISEN4N: PC7329.2 PU7.25(ISEN4N) ; also on sheet 33
PVCCIN_CPU1_ISEN4P: PC7329.1 PU7.26(ISEN4P) ; also on sheet 33
PVCCIN_CPU1_ISEN5N: PC7330.2 PU7.23(ISEN5N) ; also on sheet 33
PVCCIN_CPU1_ISEN5P: PC7330.1 PU7.24(ISEN5P) ; also on sheet 33
PVCCIN_CPU1_PG: PR1954.1 PR1958.1 PU7.9(VR_READY)
PVCCIN_CPU1_PHASE1: PC1420.2 PU184.7(PHASE)
PVCCIN_CPU1_PHASE1_R: PC1420.1 PR2223.2
PVCCIN_CPU1_PHASE2: PC1411.2 PU183.7(PHASE)
PVCCIN_CPU1_PHASE2_R: PC1411.1 PR2225.2
PVCCIN_CPU1_PHASE3: PC1446.2 PU185.7(PHASE)
PVCCIN_CPU1_PHASE3_R: PC1446.1 PR2237.2
PVCCIN_CPU1_PWM1: PU7.3(PWM1) PU184.1(PWM)
PVCCIN_CPU1_PWM2: PU7.4(PWM2) PU183.1(PWM)
PVCCIN_CPU1_PWM3: PU7.5(PWM3) PU185.1(PWM)
PVCCIN_CPU1_PWM4: PU7.6(PWM4) ; also on sheet 33
PVCCIN_CPU1_PWM5: PU7.7(PWM5) ; also on sheet 33
PVCCIN_CPU1_SADDRL: PR1964.1 PU7.30(SADDR_L)
PVCCIN_CPU1_SADDRM: PR1963.1 PU7.27(SADDR_M)
PVCCIN_CPU1_SW#1: PG41.2 PL81.1(S) PU184.16(SW#16) PU184.17(SW#17) PU184.18(SW#18) PU184.19(SW#19) PU184.20(SW#20) PU184.21(SW#21) PU184.22(SW#22) PU184.23(SW#23) PU184.24(NC#24) PU184.25(NC#25) PU184.26(NC#26)
PVCCIN_CPU1_SW#1_N: PG41.1 PR6639.2
PVCCIN_CPU1_SW#1_R: PR6639.1 PR6640.1
PVCCIN_CPU1_SW#2: PG47.2 PL80.1(S) PU183.16(SW#16) PU183.17(SW#17) PU183.18(SW#18) PU183.19(SW#19) PU183.20(SW#20) PU183.21(SW#21) PU183.22(SW#22) PU183.23(SW#23) PU183.24(NC#24) PU183.25(NC#25) PU183.26(NC#26)
PVCCIN_CPU1_SW#2_N: PG47.1 PR6638.2
PVCCIN_CPU1_SW#2_R: PR6637.1 PR6638.1
PVCCIN_CPU1_SW#3: PG55.2 PL82.1(S) PU185.16(SW#16) PU185.17(SW#17) PU185.18(SW#18) PU185.19(SW#19) PU185.20(SW#20) PU185.21(SW#21) PU185.22(SW#22) PU185.23(SW#23) PU185.24(NC#24) PU185.25(NC#25) PU185.26(NC#26)
PVCCIN_CPU1_SW#3_N: PG55.1 PR6642.2
PVCCIN_CPU1_SW#3_R: PR6641.1 PR6642.1
PVCCIN_CPU1_TMON1: PR29.1 PU184.30(PHFLT#)
PVCCIN_CPU1_TMON2: PR30.1 PU183.30(PHFLT#)
PVCCIN_CPU1_TMON3: PR31.1 PU185.30(PHFLT#)
PVCCIN_CPU1_TSEN: PC1586.2 PR1937.1 PU7.33(TSEN)
PVCCIN_CPU1_TSEN_R: PC1460.2 PQ7.E PR1937.2
PVCCIN_CPU1_VADDR: PR1962.1 PU7.17(VADDR)
PVCCIN_CPU1_VCC1: PC1443.2 PR2193.2 PR2233.2 PU184.3(VCC)
PVCCIN_CPU1_VCC2: PC1418.2 PR2190.2 PR2232.2 PU183.3(VCC)
PVCCIN_CPU1_VCC3: PC1454.2 PR2196.2 PR2234.2 PU185.3(VCC)
PVCCIN_CPU1_VCLK: PR1976.1 PU7.13(VCLK)
PVCCIN_CPU1_VD15: PC1225.1 PC1226.1 PU7.48(VD15)
PVCCIN_CPU1_VDD: PC1223.1 PC1224.1 PR1951.2 PU7.37(VDD)
PVCCIN_CPU1_VDIO: PR1975.1 PU7.14(VDIO)
PVCCIN_CPU1_VIN: PC1412.1 PC1413.1 PC1414.1 PC1415.1 PC1416.1 PC1421.1 PC1422.1 PC1438.1 PC1439.1 PC1440.1 PC1441.1 PC1442.1 PC1447.1 PC1448.1 PC1449.1 PC1450.1 PC1451.1 PC1452.1 PR1965.1 PU183.8(VIN) PU183.9(VIN) PU183.10(VIN) PU183.11(VIN) PU183.33(VIN) PU184.8(VIN) PU184.9(VIN) PU184.10(VIN) PU184.11(VIN) PU184.33(VIN) PU185.8(VIN) PU185.9(VIN) PU185.10(VIN) PU185.11(VIN) PU185.33(VIN) ; also on sheet 32 33
PVCCIN_CPU1_VINSEN: PC1230.2 PR1965.2 PR1966.2 PU7.36(VINSEN)
PVCCIN_CPU1_VR_EN: PR1957.1 PU7.10(VR_EN)
PVCCIN_CPU1_VSENN: PC1232.2 PR1969.2 PU7.19(VSENN)
PVCCIN_CPU1_VSENP: PC1232.1 PR1967.2 PU7.18(VSENP)
PVCCIN_CPU1_ZCD#1: PR2233.1 PU184.2(NC#2)
PVCCIN_CPU1_ZCD#2: PR2232.1 PU183.2(NC#2)
PVCCIN_CPU1_ZCD#3: PR2234.1 PU185.2(NC#2)
PVCCIO: PC1231.1 PC1233.1 PR1971.1 PR1972.1 PR1973.1 ; also on sheet 11 16 26 39 46 47 68 87 97 100 101 102 103 120 129 130 139 160 173 177 179 182
IRQ_PVCCIN_CPU1_VRHOT_LVT3_N: PR1955.1 PU7.47(VR_HOT#) ; also on sheet 177 181
PWRGD_PVCCIN_CPU1: PR1958.2 ; also on sheet 51
SMB_VR_STBY_LVC3_CLK: PU7.12(SCL) ; also on sheet 16 21 26 31 39 74 161
SMB_VR_STBY_LVC3_DATA: PU7.11(SDA) ; also on sheet 16 21 26 31 39 74 161
SVID_ALERT_CPU1_N: PR1971.2 PR1974.2 ; also on sheet 16 21 129
SVID_CLK_CPU1: PR1973.2 PR1976.2 ; also on sheet 16 21 129
SVID_DIO_CPU1: PR1972.2 PR1975.2 ; also on sheet 16 21 129
VR_FAIL_PVCC_CPU_N: PR1956.2 ; also on sheet 16 21 26 31 39 74
VSENSE_PVCCIN_CPU0_N: PR1950.2 ; also on sheet 39 130
VSENSE_PVCCIN_CPU0_P: PR1949.2 ; also on sheet 39 130
VSENSE_PVCCIN_CPU1_N: PR1969.1 ; also on sheet 32 120
VSENSE_PVCCIN_CPU1_P: PR1967.1 ; also on sheet 32 120

Not connected (* = marked no-connect by the designer): PU7 2(DNC#2)* 8(PWM6)* 16(RESET#)* 21(ISEN6P)* 40(DNC#40)* 43(DNC#43)* 45(DR_EN)*; PU181 35(GL#35)*; PU182 35(GL#35)*; PU183 35(GL#35)*; PU184 35(GL#35)*; PU185 35(GL#35)*

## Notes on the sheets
sheet 34
- PVCCIN_CPU1_MOSFET_1
- FP1007R3-R15-R
  150nH/0.29mohm/61A
  7.8*10.2*7.3 mm
- FP1007R3-R15-R
  150nH/0.29mohm/61A
  7.8*10.2*7.3 mm
- FP1007R3-R15-R
  150nH/0.29mohm/61A
  7.8*10.2*7.3 mm
sheet 35
- Power rail : PVCCIN_CPU1
  VID : 1.85 V / 1.7VbootSVID
  Controller : PX3746H
  TDC : 88 A
  Max : 190 A
  OCP : 210 A
  I2C address : 24
  SVID address : 00
  Platform : Grantley-EP 2S/4S skt R3
  CPU : HSX/BDX-EP 2S 145W
- Come from INFINEON  PX3746 datasheet
- Routed As Differential Pair
- Routed As Differential Pair
- Routed As Differential Pair
- Routed As Differential Pair
- Routed As Differential Pair
- Measurement point for Bode
- CPU1 I2C address:24
- Routed As Differential Pair
- close Phase 1 between phase 2
- PDG P.252
sheet 36
- PVCCIN CPU0 Decoupling
- Place in CPU Socket Cavity
- Place Capacitors Under Output Inductors on Bottom Side
- 25x22uF place on BOTTOM side PCB inside CPU socket cavity
- Place After Lout
- Place Capcitors Around Outside CPU Socket
- 17x47uF place on TOP side PCB inside CPU socket cavity
- CPU0 LC Filter
- 4x22uF place on TOP side PCB inside CPU socket cavity
- 2x1uF place on Bottom side PCB
   inside CPU socket cavity
- To Remote Sense
- Routed As Differential Pair
- To Local Sense
sheet 37
- PVCCIN_CPU0_MOSFET_2
- FP1007R3-R15-R
  150nH/0.29mohm/61A
  7.8*10.2*7.3 mm
- FP1007R3-R15-R
  150nH/0.29mohm/61A
  7.8*10.2*7.3 mm
